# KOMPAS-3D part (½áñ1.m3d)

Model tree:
1. Эскиз:1
2. Операция выдавливания:1
     Расстояние 1 = 20
3. Эскиз:2
4. Операция выдавливания:2
     Расстояние 1 = 400
5. Эскиз:3
6. Вырезать элемент выдавливания:1
     Расстояние 1 = 70
7. Эскиз:4
8. Вырезать элемент выдавливания:2
     Расстояние 1 = 2
9. Эскиз:5
10. Эскиз:6
11. Вырезать элемент выдавливания:3
     Расстояние 2 = 40; Расстояние 1 = 36
12. Эскиз:9
13. Вырезать элемент выдавливания:5
     Расстояние 1 = 40
14. Эскиз:10
15. Вырезать элемент выдавливания:6
     Расстояние 1 = 40
